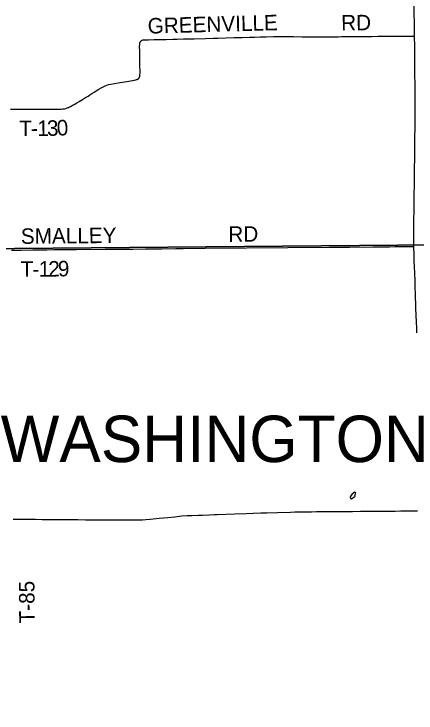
# Model space of a CAD drawing. Extents: x -87 to 2145, y -2128 to 440.
# Drawn here: x 261.3 to 300.2, y -365.9 to -298.2 of the extents above; entities that cross this region are included whole.
import ezdxf

# ---------------------------------------------------------------- set-up
doc = ezdxf.new("R2010")
doc.units = 0
for name, color, linetype in [('GM_X_County_Road', 7, 'Continuous'), ('GM_X_Minor_Lake_Text', 7, 'Continuous'), ('GM_X_Township', 7, 'Continuous'), ('GM_X_Township_Road', 7, 'Continuous'), ('GM_X_Township_Road_Text', 7, 'Continuous'), ('GM_X_Township_Text', 7, 'Continuous')]:
    doc.layers.add(name, color=color, linetype=linetype)

msp = doc.modelspace()

# ---------------------------------------------------------------- linework, layer by layer
at = {"layer": 'GM_X_County_Road'}
for points in [[(300.069, -300.368), (300.062, -299.804), (300.055, -299.115), (300.041, -298.147), (300.019, -297.245), (300.016, -297), (300.008, -296.622), (300.008, -295.918), (300.002, -295.72), (299.987, -295.081), (299.97, -294.36), (299.971, -294.24)], [(300.012, -320.761), (300.006, -320.501), (299.995, -320.14), (299.992, -319.858), (299.989, -319.616), (299.986, -319.298), (299.983, -319.027), (300.004, -318.125), (300.018, -317.288), (300.024, -316.862), (300.029, -316.468), (300.04, -315.566), (300.052, -314.976), (300.058, -314.057), (300.065, -313.434), (300.07, -313.172), (300.075, -312.959), (300.085, -312.417), (300.096, -311.5), (300.103, -310.86), (300.102, -310.056), (300.113, -309.368), (300.118, -308.974), (300.129, -308.17), (300.129, -307.776), (300.126, -307.53), (300.118, -306.825), (300.111, -305.841), (300.111, -305.201), (300.099, -303.955), (300.093, -303.397), (300.082, -301.28), (300.071, -300.509), (300.069, -300.368)], [(300.287, -329.103), (300.276, -328.826), (300.254, -327.908), (300.239, -327.564), (300.206, -326.564), (300.163, -325.432), (300.131, -324.58), (300.114, -324.138), (300.079, -323.222), (300.065, -322.78), (300.039, -322.042), (300.027, -321.616), (300.012, -320.761)], [(261.211, -347.169), (261.391, -347.167), (262.064, -347.173), (262.391, -347.174), (262.85, -347.175), (263.359, -347.18), (263.999, -347.187), (264.343, -347.19), (265.064, -347.195), (265.392, -347.196), (265.998, -347.195), (266.425, -347.198), (267.458, -347.208), (268.196, -347.215), (268.885, -347.223), (269.574, -347.227), (270.575, -347.236), (271.083, -347.239), (271.362, -347.241), (271.936, -347.242), (272.657, -347.242), (273.329, -347.238), (273.722, -347.224), (274.049, -347.204), (274.457, -347.169), (275.354, -347.077), (276.17, -346.994), (276.856, -346.924), (277.542, -346.858), (278.066, -346.819), (278.492, -346.798), (279.165, -346.778), (279.542, -346.765), (280.214, -346.739), (280.656, -346.723), (280.968, -346.713), (282.671, -346.644), (283.752, -346.603), (284.441, -346.579), (285.179, -346.557), (285.769, -346.541), (286.786, -346.51), (288.049, -346.479), (288.491, -346.469), (289.376, -346.451), (290.08, -346.443), (290.589, -346.439), (291.688, -346.429), (292.705, -346.421), (293.41, -346.415), (294.066, -346.409), (294.821, -346.404), (295.493, -346.396), (295.936, -346.396), (296.379, -346.392), (297.117, -346.383), (297.625, -346.378), (298.183, -346.377), (298.724, -346.373), (299.315, -346.368), (299.659, -346.37), (300.2, -346.369), (300.348, -346.367)]]:
    msp.add_lwpolyline(points, dxfattribs=at)
at = {"layer": 'GM_X_Minor_Lake_Text'}
for p, q in [((294.269, -344.563), (293.996, -344.77)), ((294.369, -344.635), (294.269, -344.563)), ((294.296, -344.854), (294.369, -344.635)), ((293.996, -344.77), (293.842, -345.018)), ((293.842, -345.018), (293.86, -345.179)), ((293.86, -345.179), (293.951, -345.18)), ((293.951, -345.18), (294.325, -344.944)), ((294.325, -344.944), (294.296, -344.854))]:
    msp.add_line(p, q, dxfattribs=at)
at = {"layer": 'GM_X_Township'}
msp.add_lwpolyline([(342.126, -320.177), (342.126, -234.663), (246.785, -234.663), (246.77, -241.197), (246.69, -254.507), (246.571, -267.741), (246.483, -287.008), (246.441, -294.207), (246.471, -321.06), (339.281, -320.272)], close=True, dxfattribs=at)
msp.add_lwpolyline([(342.126, -424.062), (342.126, -320.177), (339.281, -320.272), (246.471, -321.06), (233.09, -320.764), (226.827, -320.718), (226.147, -320.71), (220.66, -320.641), (220.796, -334.306), (220.92, -346.926), (221.05, -360.125), (221.093, -364.423)], dxfattribs=at)
at = {"layer": 'GM_X_Township_Road'}
for points in [[(260.96, -307.447), (261.96, -307.443), (262.551, -307.442), (263.01, -307.445), (263.289, -307.443), (263.781, -307.443), (264.289, -307.441), (264.928, -307.442), (265.338, -307.442), (265.65, -307.438), (265.863, -307.433), (266.026, -307.421), (266.172, -307.4), (266.3, -307.37), (266.424, -307.329), (266.528, -307.288), (266.573, -307.269), (266.676, -307.219), (266.762, -307.174), (266.82, -307.144), (267.005, -307.04), (267.103, -306.982), (267.368, -306.817), (267.581, -306.694), (267.907, -306.504), (268.202, -306.327), (268.452, -306.17), (268.619, -306.066), (268.812, -305.943), (269.049, -305.798), (269.258, -305.669), (269.494, -305.52), (269.73, -305.372), (269.916, -305.268), (270.108, -305.175), (270.276, -305.109), (270.449, -305.058), (270.657, -305.012), (271.368, -304.888), (272.404, -304.719), (272.906, -304.634), (273.095, -304.596), (273.149, -304.582), (273.189, -304.571), (273.217, -304.562), (273.259, -304.545), (273.289, -304.53), (273.312, -304.518), (273.331, -304.504), (273.349, -304.49), (273.358, -304.482), (273.368, -304.472), (273.379, -304.459), (273.389, -304.445), (273.406, -304.418), (273.42, -304.389), (273.434, -304.356), (273.446, -304.328), (273.455, -304.298), (273.46, -304.279), (273.466, -304.253), (273.473, -304.218), (273.48, -304.168), (273.484, -304.104), (273.49, -303.923), (273.479, -303.07), (273.469, -302.283), (273.46, -301.807), (273.45, -301.38), (273.455, -301.197), (273.464, -301.085), (273.478, -301.019), (273.486, -300.99), (273.499, -300.96), (273.519, -300.924), (273.541, -300.888), (273.565, -300.86), (273.597, -300.828), (273.633, -300.8), (273.667, -300.779), (273.706, -300.761), (273.748, -300.743), (273.808, -300.735), (273.924, -300.724), (274.07, -300.717), (274.317, -300.715), (274.842, -300.711), (275.645, -300.694), (276.023, -300.685), (276.662, -300.669), (277.072, -300.661), (277.712, -300.647), (278.449, -300.624), (278.728, -300.616), (279.827, -300.59), (280.565, -300.57), (281.007, -300.556), (282.598, -300.508), (283.368, -300.491), (284.073, -300.474), (284.582, -300.464), (285.123, -300.452), (285.385, -300.445), (285.713, -300.435), (286.401, -300.415), (287.073, -300.414), (287.663, -300.416), (288.335, -300.418), (289.188, -300.423), (289.729, -300.427), (290.287, -300.43), (290.812, -300.433), (291.288, -300.432), (291.714, -300.433), (292.14, -300.433), (292.664, -300.424), (292.992, -300.419), (293.221, -300.414), (293.779, -300.404), (294.434, -300.406), (295.287, -300.398), (295.927, -300.391), (296.501, -300.385), (297.863, -300.379), (298.42, -300.376), (299.224, -300.369), (299.896, -300.368), (300.069, -300.368)], [(261.053, -321.103), (261.971, -321.091), (263.12, -321.077), (263.792, -321.066), (264.465, -321.062), (265.138, -321.053), (266.22, -321.042), (267.336, -321.036), (270.108, -321.015), (270.732, -321.009), (271.913, -321.003), (272.799, -320.994), (274.029, -320.978), (275.555, -320.974), (276.949, -320.951), (277.655, -320.945), (279.803, -320.912), (291.79, -320.817), (292.594, -320.816), (293.119, -320.811), (293.759, -320.81), (294.776, -320.798), (295.268, -320.799), (296.023, -320.796), (297.122, -320.787), (297.647, -320.778), (298.187, -320.766), (298.695, -320.759), (299.548, -320.757), (300.012, -320.761)]]:
    msp.add_lwpolyline(points, dxfattribs=at)

# ---------------------------------------------------------------- texts
at = {"layer": 'GM_X_Township_Road_Text'}
for s, rotation, p in [('GREENVILLE', 1.54485, (274.249, -300.129)), ('RD', 0.4852, (292.966, -299.822)), ('T', 0.3, (261.803, -310.055)), ('1', 0.54112, (263.547, -310.045)), ('3', 1.2132, (264.491, -310.036)), ('0', 2.95711, (265.464, -310.015)), ('-', 0.34898, (262.926, -310.049)), ('SMALLEY', 0.57684, (261.959, -320.501)), ('RD', 0.49364, (282.046, -320.304)), ('T', 0.59141, (261.948, -323.695)), ('1', 0.63009, (263.687, -323.677)), ('2', 0.77633, (264.615, -323.667)), ('9', 1.28223, (265.553, -323.654)), ('-', 0.59144, (263.07, -323.683)), ('T-85', 90.34751, (263.292, -357.263))]:
    msp.add_text(s, height=1.5, rotation=rotation, dxfattribs=at).set_placement(p)
at = {"layer": 'GM_X_Township_Text'}
msp.add_text('WASHINGTON', height=4.5, rotation=0.00001, dxfattribs=at).set_placement((259.997, -341.637))

doc.saveas('drawing.dxf')
